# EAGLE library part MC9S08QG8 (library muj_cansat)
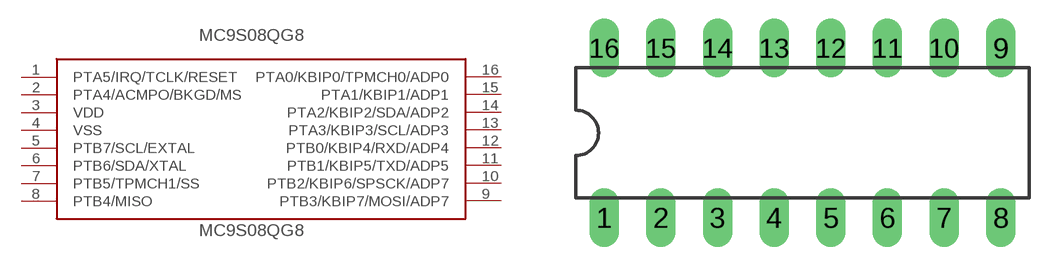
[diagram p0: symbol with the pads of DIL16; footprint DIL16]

Designator prefix D

## MC9S08QG8  [DIL16]
1  PTA5/IRQ/TCLK/RESET
2  PTA4/ACMPO/BKGD/MS
3  VDD  pwr
4  VSS  pwr
5  PTB7/SCL/EXTAL
6  PTB6/SDA/XTAL
7  PTB5/TPMCH1/SS
8  PTB4/MISO
9  PTB3/KBIP7/MOSI/ADP7
10  PTB2/KBIP6/SPSCK/ADP7
11  PTB1/KBIP5/TXD/ADP5
12  PTB0/KBIP4/RXD/ADP4
13  PTA3/KBIP3/SCL/ADP3
14  PTA2/KBIP2/SDA/ADP2
15  PTA1/KBIP1/ADP1
16  PTA0/KBIP0/TPMCH0/ADP0

## Footprint DIL16 (pad centres in mm)
Dual In Line Package
drill 0.813 long: 1 -8.89,-3.81; 2 -6.35,-3.81; 3 -3.81,-3.81; 4 -1.27,-3.81; 5 1.27,-3.81; 6 3.81,-3.81; 7 6.35,-3.81; 8 8.89,-3.81; 9 8.89,3.81; 10 6.35,3.81; 11 3.81,3.81; 12 1.27,3.81; 13 -1.27,3.81; 14 -3.81,3.81; 15 -6.35,3.81; 16 -8.89,3.81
